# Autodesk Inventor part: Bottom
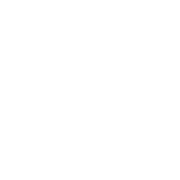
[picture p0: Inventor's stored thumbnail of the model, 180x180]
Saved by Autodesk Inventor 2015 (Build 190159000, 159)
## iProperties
Created: 2016-02
Part Number: Bottom
Material: Wood (Birch)
Document SubType Name: Modeling
Designer: Hafliði
Density: 0.55 g/cm^3
Appearance: Birch - Natural Polished
Author: Hafliði
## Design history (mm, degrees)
sketch "Sketch1"
  geometry: L1 (-360, 150)-(360, 150); L2 (360, 150)-(360, -150); L3 (360, -150)-(-360, -150); L4 (-360, -150)-(-360, 150); L5 (-360, 150)-(360, -150); L6 (360, 150)-(-360, -150); 1 further point
  constraints: 12 end point, 2 midpoint, 2 parallel, 1 horizontal, 1 perpendicular
  dimensions: "d0" = 720 distance of L2.end L3.end; "d1" = 300 distance of L1.end L2.end
extrude "Extrusion1" new body sketch "Sketch1" distance "d2" = 10; taper "d3" = 0 deg
body "Solid1"
